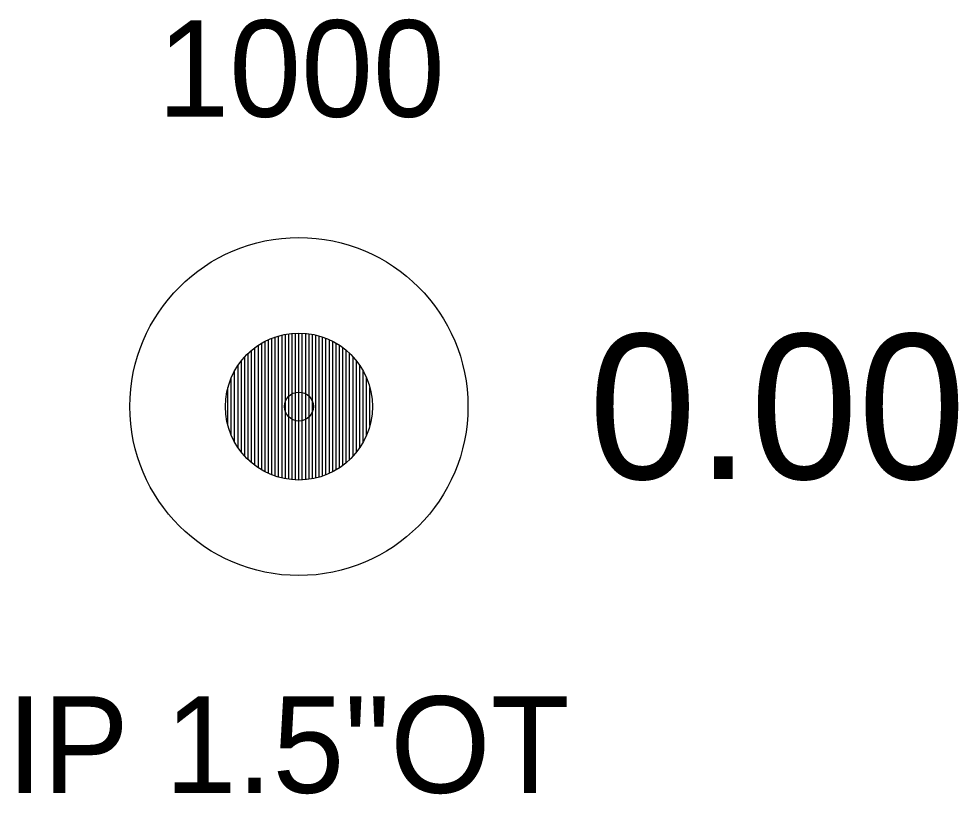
# Model space of a CAD drawing. Extents: x 1762456 to 1764480, y 822234 to 826541.
# Drawn here: x 1763625.16 to 1763634.88, y 826532.94 to 826540.96 of the extents above; entities that cross this region are included whole.
import ezdxf

# ---------------------------------------------------------------- set-up
doc = ezdxf.new("R2010")
doc.units = 0
for name, color, linetype in [('RD_EX_DV_Prop_txCode', 7, 'Continuous'), ('RD_EX_DV_PropPin', 7, 'Continuous'), ('RD_EX_TX_DV_Prop_ELEV', 7, 'Continuous'), ('RD_SMD_Locator', 7, 'Continuous')]:
    doc.layers.add(name, color=color, linetype=linetype)

msp = doc.modelspace()

# ---------------------------------------------------------------- linework, layer by layer
at = {"layer": 'RD_EX_DV_PropPin'}
for p, q in [((1763627.7064, 826536.274), (1763627.7064, 826537.6254)), ((1763627.7415, 826536.257), (1763627.7415, 826537.6424)), ((1763627.7765, 826536.2421), (1763627.7765, 826537.6573)), ((1763627.8115, 826536.2292), (1763627.8115, 826537.6702)), ((1763627.8465, 826536.2183), (1763627.8465, 826537.6811)), ((1763627.8815, 826536.2091), (1763627.8815, 826537.6903)), ((1763627.9165, 826536.2017), (1763627.9165, 826537.6977)), ((1763627.9515, 826536.196), (1763627.9515, 826537.7034)), ((1763627.9866, 826536.1919), (1763627.9866, 826537.7075)), ((1763628.0216, 826536.1895), (1763628.0216, 826537.7099)), ((1763628.0566, 826536.1887), (1763628.0566, 826537.7107)), ((1763628.0916, 826536.1895), (1763628.0916, 826537.7099)), ((1763628.1266, 826536.1919), (1763628.1266, 826537.7075)), ((1763628.1616, 826536.196), (1763628.1616, 826537.7034)), ((1763628.1966, 826536.2017), (1763628.1966, 826537.6977)), ((1763628.2316, 826536.2091), (1763628.2316, 826537.6903)), ((1763628.2667, 826536.2183), (1763628.2667, 826537.6811)), ((1763628.3017, 826536.2292), (1763628.3017, 826537.6702)), ((1763628.3367, 826536.2421), (1763628.3367, 826537.6573)), ((1763628.3717, 826536.257), (1763628.3717, 826537.6424)), ((1763628.4067, 826536.274), (1763628.4067, 826537.6254)), ((1763627.5664, 826536.3676), (1763627.5664, 826537.5318)), ((1763627.6014, 826536.3398), (1763627.6014, 826537.5596)), ((1763627.6364, 826536.3152), (1763627.6364, 826537.5842)), ((1763627.6714, 826536.2933), (1763627.6714, 826537.6061)), ((1763628.4417, 826536.2933), (1763628.4417, 826537.6061)), ((1763628.4767, 826536.3152), (1763628.4767, 826537.5842)), ((1763628.5118, 826536.3398), (1763628.5118, 826537.5596)), ((1763628.5468, 826536.3676), (1763628.5468, 826537.5318)), ((1763627.4964, 826536.4346), (1763627.4964, 826537.4648)), ((1763627.5314, 826536.399), (1763627.5314, 826537.5004)), ((1763628.5818, 826536.399), (1763628.5818, 826537.5004)), ((1763628.6168, 826536.4346), (1763628.6168, 826537.4648)), ((1763627.4263, 826536.5232), (1763627.4263, 826537.3762)), ((1763627.4613, 826536.4755), (1763627.4613, 826537.4239)), ((1763628.6518, 826536.4755), (1763628.6518, 826537.4239)), ((1763628.6868, 826536.5232), (1763628.6868, 826537.3762)), ((1763627.3563, 826536.6518), (1763627.3563, 826537.2476)), ((1763627.3913, 826536.5802), (1763627.3913, 826537.3192)), ((1763628.7218, 826536.5802), (1763628.7218, 826537.3192)), ((1763628.7569, 826536.6518), (1763628.7569, 826537.2476)), ((1763627.3213, 826536.7535), (1763627.3213, 826537.1459)), ((1763628.7919, 826536.7535), (1763628.7919, 826537.1459))]:
    msp.add_line(p, q, dxfattribs=at)
for radius in [1.75, 0.761]:
    msp.add_circle((1763628.0566, 826536.9497), radius, dxfattribs=at)
at = {"layer": 'RD_SMD_Locator'}
msp.add_circle((1763628.0566, 826536.9497), 0.15, dxfattribs=at)

# ---------------------------------------------------------------- texts
at = {"layer": 'RD_EX_DV_Prop_txCode'}
for s, p in [('1000', (1763626.592, 826539.9497)), ('IP 1.5"OT', (1763625.033, 826532.9497))]:
    msp.add_text(s, height=1, dxfattribs=at).set_placement(p)
at = {"layer": 'RD_EX_TX_DV_Prop_ELEV'}
msp.add_text('0.00', height=1.5, dxfattribs=at).set_placement((1763631.0566, 826536.1997))

doc.saveas('drawing.dxf')
